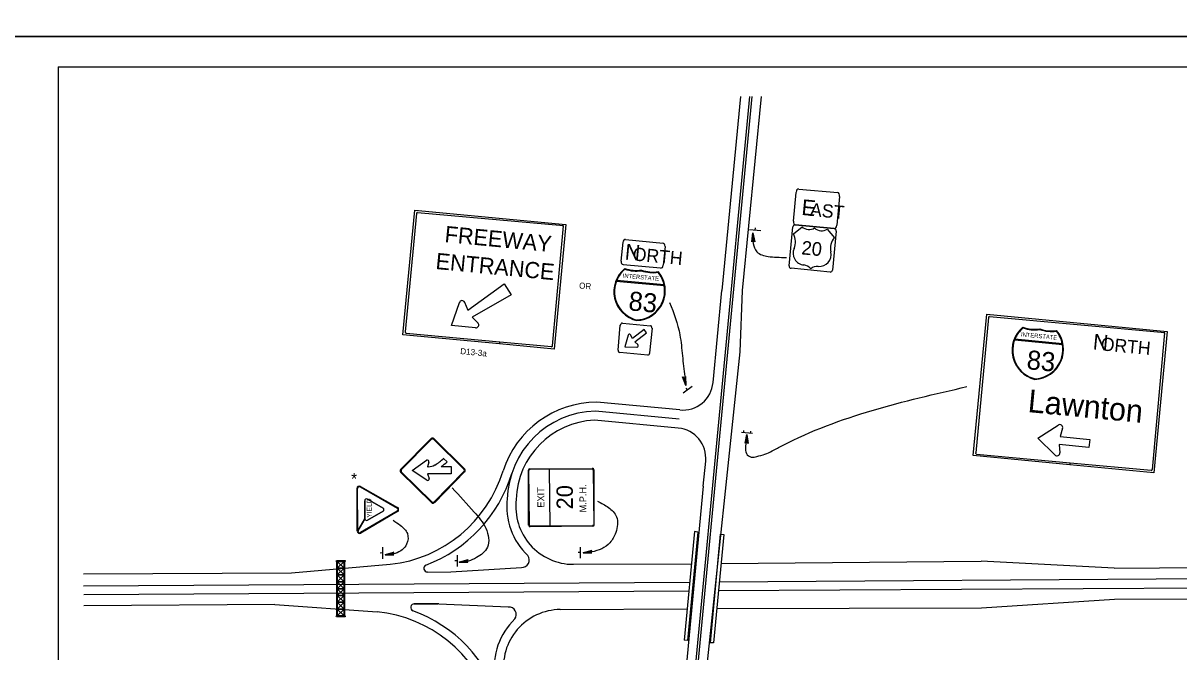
# Model space of a CAD drawing. Extents: x 644898 to 648326, y 298294 to 300670.
# Drawn here: x 647444 to 648015, y 299772 to 300083 of the extents above; entities that cross this region are included whole.
import ezdxf

# ---------------------------------------------------------------- set-up
doc = ezdxf.new("R2010")
doc.units = 0
for name, color, linetype in [('1', 7, 'Continuous'), ('2', 7, 'Continuous'), ('XCS-GRID-MIN', 7, 'Continuous')]:
    doc.layers.add(name, color=color, linetype=linetype)

msp = doc.modelspace()

# ---------------------------------------------------------------- linework, layer by layer
at = {"layer": '1'}
for q in [(648247.32, 300061.49), (647461.32, 299497.49)]:
    msp.add_line((647461.32, 300061.49), q, dxfattribs=at)
at = {"layer": '2'}
for p, q in [((647802.82, 300046.87), (647766.22, 299662.87)), ((647803.95, 300046.87), (647767.34, 299662.77)), ((647798.32, 300046.87), (647789.07, 299950.99)), ((647808.45, 300046.87), (647799.2, 299950.99)), ((647824.45, 299985.24), (647825.82, 299999.49)), ((647827.07, 300001.12), (647846.32, 299999.37)), ((647847.2, 299997.49), (647845.82, 299983.24)), ((647631.52, 299929.13), (647637.45, 299990.69)), ((647638.33, 299989.06), (647632.78, 299930.56)), ((647637.45, 299990.68), (647712.1, 299983.56)), ((647835.82, 299991.37), (647835.82, 299991.37)), ((647705.52, 299923.65), (647710.92, 299982.9)), ((647712.1, 299983.56), (647706.3, 299922.01)), ((647824.45, 299978.99), (647828.7, 299982.49)), ((647844.57, 299981.62), (647825.32, 299983.37)), ((647825.32, 299983.37), (647844.57, 299981.62)), ((647808.32, 299980.49), (647802.82, 299980.99)), ((647805.57, 299980.87), (647805.7, 299981.87)), ((647822.32, 299963.12), (647824.07, 299982.37)), ((647841.07, 299981.24), (647844.7, 299976.99)), ((647845.57, 299980.37), (647843.7, 299960.99)), ((647739.45, 299965.48), (647740.32, 299974.8)), ((647741.53, 299976.15), (647760.05, 299974.37)), ((647761.03, 299972.77), (647760.2, 299963.48)), ((647833.95, 299971.74), (647833.95, 299971.74)), ((647843.07, 299968.12), (647843.07, 299968.12)), ((647758.82, 299961.98), (647740.45, 299963.73)), ((647741.22, 299961.52), (647741.22, 299961.52)), ((647749.35, 299960.77), (647749.35, 299960.77)), ((647757.6, 299960.02), (647757.6, 299960.02)), ((647842.57, 299960.12), (647823.32, 299961.99)), ((647829.57, 299963.62), (647829.57, 299963.62)), ((647836.7, 299962.87), (647836.7, 299962.87)), ((647663.73, 299941.26), (647681.58, 299954.31)), ((647681.58, 299954.31), (647685.14, 299948.81)), ((647736.97, 299955.65), (647760.6, 299953.4)), ((647760.6, 299953.77), (647737.22, 299955.9)), ((647685.14, 299948.81), (647665.85, 299937.86)), ((647784.78, 299905.51), (647789.07, 299950.99)), ((647799.2, 299950.99), (647797.95, 299920.74)), ((647655.67, 299933.64), (647659.51, 299945.02)), ((647662.05, 299945.23), (647663.73, 299941.26)), ((647665.85, 299937.86), (647668.78, 299934.88)), ((647913.21, 299869.4), (647919.93, 299939.29)), ((647920.81, 299937.66), (647914.46, 299870.81)), ((647919.93, 299939.28), (648009.06, 299930.78)), ((647667.49, 299932.51), (647655.67, 299933.64)), ((647737.83, 299921.55), (647738.93, 299933.83)), ((647739.99, 299934.85), (647753.82, 299933.53)), ((647750.82, 299931.71), (647744.91, 299927.3)), ((647751.96, 299930.06), (647750.82, 299931.71)), ((647754.66, 299932.36), (647753.41, 299920.12)), ((647937.85, 299932.44), (647937.85, 299932.44)), ((647946.1, 299931.69), (647946.1, 299931.69)), ((647679.32, 299924.58), (647631.52, 299929.13)), ((647633.18, 299929.91), (647679.42, 299925.59)), ((647679.32, 299924.58), (647679.42, 299925.59)), ((647679.42, 299925.59), (647679.32, 299924.58)), ((647679.42, 299925.59), (647704.93, 299923.31)), ((647742.79, 299928.92), (647741.22, 299923.19)), ((647744.91, 299927.3), (647743.98, 299929.05)), ((647746.2, 299925.6), (647751.96, 299930.06)), ((647747.72, 299924.16), (647746.2, 299925.6)), ((647933.73, 299926.57), (647957.23, 299924.32)), ((647957.23, 299924.69), (647933.85, 299926.94)), ((647954.23, 299930.94), (647954.23, 299930.94)), ((648001.68, 299862.54), (648007.87, 299930.12)), ((648009.06, 299930.78), (648002.46, 299860.9)), ((647706.3, 299922.01), (647679.32, 299924.58)), ((647752.51, 299919.05), (647738.67, 299920.37)), ((647741.22, 299923.19), (647747.21, 299923.01)), ((647797.95, 299920.74), (647780.45, 299754.37)), ((647774.5, 299903.54), (647769.96, 299900.19)), ((647772.18, 299901.83), (647771.53, 299902.75)), ((647768, 299887.49), (647726.65, 299891.41)), ((647768.42, 299891.99), (647727.41, 299895.9)), ((647767.59, 299882.99), (647726.14, 299886.91)), ((647756.07, 299888.62), (647756.07, 299888.62)), ((647804.27, 299880.26), (647798.77, 299880.76)), ((647799.9, 299880.63), (647799.9, 299881.76)), ((647803.27, 299880.38), (647803.4, 299881.51)), ((647945.09, 299878.06), (647955.24, 299884.48)), ((647957.35, 299883.04), (647956.15, 299878.9)), ((647630.45, 299862.62), (647645.57, 299877.87)), ((647630.95, 299862.49), (647645.57, 299877.37)), ((647646.82, 299877.37), (647661.7, 299862.74)), ((647646.95, 299877.87), (647662.2, 299862.74)), ((647953.56, 299869.74), (647945.09, 299878.06)), ((647970.31, 299873.34), (647955.66, 299874.93)), ((647955.66, 299874.93), (647956.05, 299870.77)), ((647956.15, 299878.9), (647970.8, 299877.31)), ((647970.8, 299877.31), (647970.31, 299873.34)), ((647961.01, 299864.84), (647913.21, 299869.4)), ((647914.87, 299870.18), (647961.1, 299865.85)), ((647636.2, 299862.12), (647643.32, 299867.12)), ((647636.2, 299862.12), (647643.32, 299867.12)), ((647644.45, 299866.24), (647643.82, 299863.87)), ((647644.45, 299866.24), (647643.82, 299863.87)), ((647643.82, 299863.87), (647644.2, 299863.99)), ((647643.82, 299863.87), (647644.2, 299863.99)), ((647650.57, 299863.99), (647655.45, 299863.99)), ((647650.57, 299863.99), (647650.57, 299863.99)), ((647650.57, 299863.99), (647655.45, 299863.99)), ((647651.7, 299867.99), (647653.45, 299866.37)), ((647651.7, 299867.99), (647653.45, 299866.37)), ((647655.45, 299863.99), (647655.45, 299860.37)), ((647655.45, 299863.99), (647655.45, 299860.37)), ((647694.2, 299862.87), (647725.2, 299863.12)), ((647694.45, 299862.74), (647724.95, 299862.87)), ((647704.32, 299834.62), (647704.07, 299862.74)), ((647779.94, 299854.28), (647781.11, 299866.65)), ((647961.01, 299864.84), (647961.1, 299865.85)), ((647961.1, 299865.85), (647961.01, 299864.84)), ((648002.46, 299860.9), (647961.01, 299864.84)), ((647961.1, 299865.85), (648001.09, 299862.2)), ((647645.82, 299846.12), (647630.45, 299861.24)), ((647645.82, 299846.62), (647630.95, 299861.24)), ((647643.45, 299857.24), (647636.2, 299862.12)), ((647643.45, 299857.24), (647636.2, 299862.12)), ((647655.45, 299860.37), (647643.82, 299860.37)), ((647643.82, 299860.37), (647644.57, 299858.12)), ((647655.45, 299860.37), (647643.82, 299860.37)), ((647643.82, 299860.37), (647644.57, 299858.12)), ((647661.7, 299861.49), (647647.07, 299846.62)), ((647662.2, 299861.49), (647647.2, 299846.12)), ((647693.7, 299834.99), (647693.57, 299862.24)), ((647694.07, 299835.24), (647693.82, 299861.99)), ((647725.57, 299862.24), (647725.82, 299835.37)), ((647725.82, 299862.37), (647725.95, 299835.24)), ((647609.07, 299832.24), (647608.95, 299853.12)), ((647609.32, 299832.24), (647609.2, 299853.12)), ((647609.32, 299832.24), (647609.2, 299853.12)), ((647610.45, 299853.99), (647628.7, 299843.49)), ((647610.45, 299853.99), (647628.7, 299843.49)), ((647610.7, 299854.12), (647628.95, 299843.74)), ((647779.95, 299854.24), (647769.7, 299745.49)), ((647612.82, 299838.24), (647612.82, 299847.12)), ((647612.82, 299847.12), (647612.82, 299838.24)), ((647614.07, 299847.87), (647621.82, 299843.49)), ((647621.82, 299843.49), (647614.07, 299847.87)), ((647779.57, 299849.74), (647779.57, 299849.74)), ((647628.82, 299841.99), (647610.7, 299831.49)), ((647628.82, 299841.99), (647610.7, 299831.49)), ((647628.95, 299841.74), (647610.82, 299831.12)), ((647621.82, 299841.99), (647614.07, 299837.49)), ((647614.07, 299837.49), (647621.82, 299841.99)), ((647612.82, 299838.24), (647609.32, 299832.24)), ((647609.32, 299832.24), (647612.82, 299838.24)), ((647612.82, 299838.24), (647612.82, 299838.24)), ((647725.32, 299834.49), (647694.45, 299834.24)), ((647725.2, 299834.74), (647694.57, 299834.49)), ((647775.57, 299831.87), (647770.45, 299778.24)), ((647777.2, 299831.62), (647772.2, 299778.12)), ((647777.2, 299831.62), (647775.57, 299831.87)), ((647788.32, 299830.62), (647783.32, 299776.99)), ((647790.07, 299830.49), (647784.95, 299776.87)), ((647788.32, 299830.62), (647790.07, 299830.49)), ((647621.57, 299824.12), (647621.57, 299818.49)), ((647719.2, 299824.24), (647719.2, 299818.74)), ((647599.2, 299817.12), (647602.57, 299813.74)), ((647602.57, 299817.12), (647599.2, 299813.74)), ((647621.57, 299821.37), (647620.32, 299821.24)), ((647658.45, 299817.37), (647657.2, 299817.37)), ((647658.32, 299820.24), (647658.45, 299814.62)), ((647719.2, 299821.49), (647718.2, 299821.49)), ((647788.57, 299816.12), (647917.17, 299817.3)), ((647982.82, 299813.87), (647917.2, 299817.24)), ((647473.9, 299810.93), (647576.57, 299811.49)), ((647576.57, 299811.49), (647625.32, 299815.74)), ((647599.2, 299813.74), (647602.57, 299810.49)), ((647602.57, 299813.74), (647599.2, 299810.49)), ((647643.82, 299811.87), (647655.32, 299811.99)), ((647655.32, 299811.99), (647690.2, 299814.12)), ((647715.82, 299815.74), (647774.07, 299815.99)), ((647715.82, 299815.74), (647715.82, 299815.74)), ((647846.82, 299816.49), (647846.82, 299816.49)), ((647982.82, 299813.87), (648204.57, 299815.27)), ((647773.2, 299806.74), (647473.96, 299804.85)), ((647599.2, 299810.49), (647602.57, 299806.99)), ((647602.57, 299810.49), (647599.2, 299806.99)), ((647599.2, 299806.99), (647602.57, 299803.62)), ((647602.57, 299806.99), (647599.2, 299803.62)), ((648204.57, 299809.66), (647787.82, 299806.87)), ((647474.01, 299800.83), (647772.82, 299802.62)), ((647599.2, 299803.62), (647602.57, 299800.37)), ((647602.57, 299803.62), (647599.2, 299800.37)), ((647599.2, 299800.37), (647602.57, 299796.99)), ((647602.57, 299800.37), (647599.2, 299796.99)), ((647787.32, 299802.74), (648204.57, 299805.13)), ((647568.35, 299795.86), (647474.07, 299795.24)), ((647568.35, 299795.86), (647618.82, 299792.24)), ((647599.2, 299796.99), (647602.57, 299793.62)), ((647602.57, 299796.99), (647599.2, 299793.62)), ((647637.2, 299796.12), (647648.82, 299796.24)), ((647649.4, 299796.21), (647637.2, 299796.12)), ((647649.4, 299796.21), (647683.57, 299794.62)), ((647982.95, 299798.24), (647917.32, 299793.99)), ((648204.57, 299799.51), (647982.95, 299798.24)), ((647599.2, 299793.62), (647602.57, 299790.24)), ((647602.57, 299793.62), (647599.2, 299790.24)), ((647602.57, 299790.24), (647602.57, 299793.62)), ((647771.95, 299793.62), (647709.32, 299793.24)), ((647713.7, 299793.24), (647713.7, 299793.24)), ((647917.32, 299793.99), (647786.57, 299793.74)), ((647772.2, 299778.12), (647770.45, 299778.24)), ((647784.95, 299776.87), (647783.32, 299776.99))]:
    msp.add_line(p, q, dxfattribs=at)
for points in [[(647710.91, 299982.9), (647638.83, 299989.43)], [(647804.03, 299975.24), (647804.3, 299975.34), (647804.33, 299979.41), (647804.03, 299975.24), (647803.86, 299975.06), (647804.33, 299979.41), (647804.83, 299975.36), (647805.09, 299975.28), (647804.33, 299979.41), (647805.37, 299975.03), (647805.09, 299975.28)], [(648007.87, 299930.12), (647921.31, 299938.03)], [(647771.02, 299908.29), (647770.78, 299908.16), (647771.37, 299904.13), (647771.02, 299908.29), (647771.17, 299908.5), (647771.37, 299904.13), (647770.26, 299908.06), (647769.98, 299908.09), (647771.37, 299904.13), (647769.67, 299908.3), (647769.98, 299908.09)], [(647800.79, 299875.73), (647801.06, 299875.81), (647801.41, 299879.86), (647800.79, 299875.73), (647800.61, 299875.56), (647801.41, 299879.86), (647801.59, 299875.78), (647801.85, 299875.68), (647801.41, 299879.86), (647802.1, 299875.41), (647801.85, 299875.68)], [(647724.71, 299821.32), (647724.6, 299821.58), (647720.54, 299821.33), (647724.71, 299821.32), (647724.91, 299821.16), (647720.54, 299821.33), (647724.54, 299822.1), (647724.6, 299822.38), (647720.54, 299821.33), (647724.84, 299822.67), (647724.6, 299822.38)], [(647598.82, 299817.12), (647598.82, 299790.24)], [(647602.57, 299817.49), (647599.2, 299817.49)], [(647599.2, 299790.24), (647602.57, 299790.24), (647602.57, 299817.12), (647599.2, 299817.12), (647599.2, 299790.24)], [(647602.95, 299790.24), (647602.95, 299817.12)], [(647626.97, 299820.41), (647626.86, 299820.67), (647622.8, 299820.42), (647626.97, 299820.41), (647627.17, 299820.26), (647622.8, 299820.42), (647626.8, 299821.2), (647626.86, 299821.47), (647622.8, 299820.42), (647627.1, 299821.76), (647626.86, 299821.47)], [(647663.53, 299816.72), (647663.41, 299816.98), (647659.35, 299816.73), (647663.53, 299816.72), (647663.72, 299816.56), (647659.35, 299816.73), (647663.36, 299817.5), (647663.42, 299817.78), (647659.35, 299816.73), (647663.65, 299818.07), (647663.42, 299817.78)], [(647599.2, 299789.87), (647602.57, 299789.87)]]:
    msp.add_lwpolyline(points, dxfattribs=at)
for points in [[(647599.2, 299813.74), (647599.2, 299817.12), (647602.57, 299817.12), (647602.57, 299813.74)], [(647599.2, 299810.49), (647599.2, 299813.74), (647602.57, 299813.74), (647602.57, 299810.49)], [(647599.2, 299806.99), (647599.2, 299810.49), (647602.57, 299810.49), (647602.57, 299806.99)], [(647599.2, 299803.62), (647599.2, 299806.99), (647602.57, 299806.99), (647602.57, 299803.62)], [(647599.2, 299800.37), (647599.2, 299803.62), (647602.57, 299803.62), (647602.57, 299800.37)], [(647599.2, 299796.99), (647599.2, 299800.37), (647602.57, 299800.37), (647602.57, 299796.99)], [(647599.2, 299793.62), (647599.2, 299796.99), (647602.57, 299796.99), (647602.57, 299793.62)], [(647599.2, 299790.24), (647599.2, 299793.62), (647602.57, 299793.62), (647602.57, 299790.24)]]:
    msp.add_lwpolyline(points, close=True, dxfattribs=at)
for centre in [(647599.02, 299817.33), (647602.8, 299817.33), (647599.02, 299790.03), (647602.8, 299790.03)]:
    msp.add_circle(centre, 0.301, dxfattribs=at)
for centre, radius, start, end in [((647638.77, 299988.98), 0.528, 84.2894, 175.6013), ((647825.22, 299982.28), 1.07, 84.5662, 174.5662), ((647832.17, 299986.34), 5.23, 227.7022, 301.4303), ((647817.34, 299975.02), 8.13, 336.3952, 29.141), ((647838.41, 299985.74), 5.23, 227.7022, 301.4303), ((647850.84, 299971.83), 8.13, 139.9915, 192.7373), ((647844.48, 299980.45), 1.07, 354.5662, 84.5662), ((647830.11, 299969.4), 5.82, 156.0183, 264.5615), ((647837.24, 299968.72), 5.82, 264.571, 13.1142), ((647750.56, 299950.48), 14.78, 129.5662, 256.4361), ((647750.56, 299950.48), 14.47, 130.2586, 157.7735), ((647746.86, 299977.87), 16.98, 250.3162, 278.8163), ((647746.86, 299977.87), 17.29, 250.9067, 278.5552), ((647746.39, 299950.88), 14.78, 272.6963, 39.5662), ((647755.19, 299977.08), 17.29, 250.5773, 278.2258), ((647755.19, 299977.08), 16.98, 250.3162, 278.8163), ((647746.39, 299950.88), 14.47, 11.359, 38.8739), ((647823.38, 299963.02), 1.07, 174.5662, 264.5662), ((647829.09, 299958.7), 4.93, 38.2937, 84.5662), ((647836.23, 299958.02), 4.93, 84.5662, 130.8388), ((647842.65, 299961.19), 1.07, 264.5662, 354.5662), ((647750.56, 299950.48), 14.47, 159.0531, 256.4361), ((647746.39, 299950.88), 14.47, 272.6964, 10.0794), ((647660.83, 299944.59), 1.4, 21.1732, 165.0799), ((647921.25, 299937.59), 0.528, 84.2894, 175.6013), ((647667.64, 299933.94), 1.4, 262.7848, 43.4503), ((647947.18, 299921.44), 14.78, 129.5662, 256.4361), ((647947.18, 299921.44), 14.47, 130.2586, 157.7735), ((647943.48, 299948.83), 16.98, 250.3162, 278.8163), ((647943.48, 299948.83), 17.29, 250.9067, 278.5552), ((647943.02, 299921.84), 14.78, 272.6963, 39.5662), ((647951.81, 299948.04), 17.29, 250.5773, 278.2258), ((647951.81, 299948.04), 16.98, 250.3162, 278.8163), ((647743.4, 299928.8), 0.625, 28.144, 164.5177), ((647947.18, 299921.44), 14.47, 159.0531, 256.4361), ((647943.02, 299921.84), 14.47, 11.359, 38.8739), ((648007.36, 299929.49), 0.528, 354.144, 84.5077), ((647747.23, 299923.67), 0.625, 267.0622, 48.6931), ((647943.02, 299921.84), 14.47, 272.6964, 10.0794), ((647769.84, 299906.92), 15, 264.5486, 354.6082), ((647727.86, 299846.67), 49.23, 90.5215, 161.9821), ((647727.86, 299846.67), 44.75, 91.5424, 178.5076), ((647727.86, 299846.67), 40.27, 92.4413, 178.5076), ((647766.18, 299868.06), 15, 354.6082, 84.6064), ((647956, 299883.32), 1.4, 342.1199, 126.0266), ((647646.23, 299877.17), 0.932, 45.3747, 135.3747), ((647646.24, 299876.78), 0.854, 45.3747, 135.3747), ((647954.57, 299870.75), 1.4, 223.7315, 4.397), ((647631.17, 299861.91), 0.932, 135.3747, 225.3747), ((647643.71, 299866.44), 0.776, 344.1725, 122.044), ((647643.71, 299866.44), 0.776, 344.1725, 122.044), ((647644.19, 299870.23), 6.31, 270.1504, 300.2643), ((647644.19, 299870.23), 6.31, 270.1504, 300.2643), ((647636.5, 299883.74), 21.86, 299.8117, 314.2596), ((647636.5, 299883.74), 21.86, 299.8117, 314.2596), ((647636.08, 299884.24), 24.91, 305.5161, 314.2639), ((647636.08, 299884.24), 24.91, 305.5161, 314.2639), ((647661.11, 299862.1), 0.854, 315.3747, 45.3747), ((647661.49, 299862.11), 0.932, 315.3747, 45.3747), ((647618.21, 299880.98), 65.66, 276.2555, 343.1031), ((647631.56, 299861.91), 0.854, 135.3747, 225.3747), ((647618.21, 299880.98), 70.14, 290.6825, 343.1031), ((647643.76, 299857.89), 0.777, 238.8177, 16.4645), ((647643.76, 299857.89), 0.777, 238.8177, 16.4645), ((647610.08, 299853.16), 1.18, 60.3746, 180.3747), ((647610.08, 299853.16), 0.871, 60.3746, 180.3747), ((647610.08, 299853.16), 0.871, 60.3746, 180.3747), ((647613.6, 299847.15), 0.871, 60.3747, 180.3747), ((647613.6, 299847.15), 0.871, 60.3747, 180.3747), ((647646.43, 299846.85), 0.932, 225.3747, 315.3747), ((647646.43, 299847.23), 0.854, 225.3747, 315.3747), ((647715.75, 299844.08), 32.86, 172.6333, 226.9648), ((647715.75, 299844.08), 28.38, 172.6333, 270.1695), ((647621.36, 299842.74), 0.871, 300.3747, 60.3746), ((647621.36, 299842.74), 0.871, 300.3747, 60.3746), ((647628.33, 299842.78), 0.871, 300.3747, 60.3746), ((647628.33, 299842.78), 0.871, 300.3747, 60.3746), ((647628.33, 299842.78), 1.18, 300.3747, 60.3746), ((647613.66, 299838.23), 0.871, 180.3746, 300.3746), ((647613.66, 299838.23), 0.871, 180.3747, 300.3746), ((647610.21, 299832.17), 1.18, 180.3747, 300.3747), ((647610.21, 299832.17), 0.871, 180.3746, 300.3747), ((647610.21, 299832.17), 0.871, 180.3746, 300.3747), ((647690.26, 299817.88), 3.76, 268.4553, 35.5225), ((647643.76, 299813.73), 1.81, 115.1781, 270.4845), ((647637.24, 299794.39), 1.81, 90.2638, 245.5703), ((647683.8, 299790.85), 3.76, 325.2259, 92.293), ((647612.58, 299726.81), 65.66, 17.6452, 84.4929), ((647612.58, 299726.81), 70.14, 17.6452, 70.0659), ((647709.62, 299764.98), 32.86, 133.7836, 188.115), ((647709.62, 299764.98), 28.38, 90.5788, 188.115)]:
    msp.add_arc(centre, radius, start, end, dxfattribs=at)
for centre, major_axis, ratio, start_param, end_param in [((647826.84, 299999.4), (-0.17, -1.78), 0.6, 3.141593, 4.712389), ((647846.11, 299997.57), (0.17, 1.78), 0.6, 4.712389, 6.283185), ((647710.41, 299982.26), (0, 0.528), 0.987556, 4.610182, 6.187326), ((647825.49, 299985.14), (-0.17, -1.78), 0.6, 4.712389, 6.283185), ((647844.75, 299983.3), (0.17, 1.78), 0.6, 3.141593, 4.712389), ((647741.44, 299974.66), (0.14, 1.52), 0.760552, 6.279242, 7.850039), ((647759.89, 299972.88), (0.14, 1.52), 0.767529, 4.711578, 6.282375), ((647740.55, 299965.36), (-0.15, -1.55), 0.769266, 4.712389, 6.283185), ((647758.98, 299963.6), (0.15, 1.55), 0.769266, 3.141593, 4.712389), ((647739.86, 299933.67), (-0.11, -1.16), 0.769266, 3.141593, 4.712389), ((647753.69, 299932.42), (0.11, 1.16), 0.769266, 4.712389, 6.283185), ((647633.26, 299930.49), (-0.556, 0), 0.992604, 6.180104, 7.77084), ((647705, 299923.71), (0, -0.496), 0.993424, 6.192525, 7.765974), ((647738.75, 299921.49), (-0.11, -1.16), 0.769266, 4.712389, 6.283185), ((647752.58, 299920.24), (0.11, 1.16), 0.769266, 3.141593, 4.712389), ((647914.94, 299870.75), (-0.558, 0), 0.963153, 6.180104, 7.77084), ((647694.22, 299862.23), (0.005, -0.717), 0.9, 3.141593, 4.712389), ((647694.41, 299862.02), (0.004, -0.657), 0.9, 3.141593, 4.712389), ((647725.01, 299862.22), (-0.004, 0.657), 0.9, 4.712389, 6.283185), ((647725.19, 299862.44), (-0.005, 0.717), 0.9, 4.712389, 6.283185), ((648001.16, 299862.6), (0.496, 0), 0.990562, 4.621729, 6.195178), ((647694.4, 299834.99), (0.005, -0.717), 0.9, 4.712389, 6.283185), ((647694.58, 299835.2), (0.004, -0.657), 0.9, 4.712389, 6.283185), ((647725.18, 299835.4), (-0.004, 0.657), 0.9, 3.141593, 4.712389), ((647725.37, 299835.19), (0.005, -0.717), 0.9, 0, 1.570796)]:
    msp.add_ellipse(centre, major_axis=major_axis, ratio=ratio, start_param=start_param, end_param=end_param, dxfattribs=at)
for points in [[(647804.32, 299979.24), (647804.57, 299974.25), (647806.39, 299970.13), (647811.96, 299967.8), (647816.2, 299967.49), (647820.95, 299967.24)], [(647763.33, 299945.12), (647768.37, 299929.05), (647769.62, 299918.72), (647770.87, 299908.48), (647771.24, 299905.36)], [(647801.28, 299878.31), (647801.19, 299876.72), (647801.22, 299870.5), (647803.64, 299868.65), (647806.39, 299869.01), (647810.4, 299870.09), (647813.96, 299871.75), (647819.04, 299874.43), (647910.14, 299903.5)], [(647655.95, 299853.49), (647666.82, 299841.49), (647672.57, 299833.49), (647673.32, 299824.12), (647668.02, 299819.03), (647663.97, 299817.34), (647661.67, 299817)], [(647727.7, 299846.87), (647733.1, 299843.75), (647737.07, 299839.24), (647736.7, 299831.37), (647733.82, 299826.37), (647724.88, 299821.83), (647721.77, 299821.45)], [(647626.82, 299837.49), (647630.32, 299834.99), (647633.82, 299830.87), (647633.45, 299825.62), (647631.32, 299822.87), (647627.82, 299821.12), (647625.12, 299820.61)]]:
    msp.add_spline(points, degree=3, dxfattribs=at)
at = {"layer": 'XCS-GRID-MIN'}
for points in [[(647421.32, 300670.49), (648262.32, 300670.49), (648262.32, 300076.49), (647421.32, 300076.49)], [(647421.32, 300076.49), (648262.32, 300076.49), (648262.32, 299482.49), (647421.32, 299482.49)]]:
    msp.add_lwpolyline(points, close=True, dxfattribs=at)

# ---------------------------------------------------------------- texts
at = {"layer": '2'}
for s, height, rotation, p in [('E', 7.75, 354.5817, (647828.2, 299988.37)), ('AST', 6.5, 354.5683, (647832.44, 299987.87)), ('FREEWAY', 8, 354.5683, (647651.98, 299974.96)), ('N', 7.75, 354.5817, (647740.98, 299966.38)), ('ORTH', 6.5, 354.5683, (647744.87, 299965.88)), ('20', 6.75, 354.5663, (647828.2, 299968.87)), ('ENTRANCE', 8, 354.5683, (647647.5, 299961.65)), ('OR', 3, 354.4706, (647718.5, 299952.03)), ('INTERSTATE', 2.089, 354.5668, (647740.1, 299957.4)), ('83', 9.406, 354.5658, (647742.72, 299941.27)), ('INTERSTATE', 2.089, 354.5668, (647936.73, 299928.32)), ('N', 7.75, 354.5817, (647972.09, 299921.94)), ('ORTH', 6.5, 354.5683, (647975.98, 299921.44)), ('D13-3a', 3, 354.4706, (647659.81, 299919.62)), ('83', 9.406, 354.5658, (647939.35, 299912.19)), ('Lawnton', 11.25, 354.5683, (647939.87, 299890.96)), ('EXIT', 3.387, 90.3745, (647701.45, 299843.74)), ('20', 8.061, 90.3746, (647715.57, 299842.87)), ('M.P.H.', 3.387, 90.3746, (647722.2, 299841.37)), ('YIELD', 2.383, 90.3738, (647616.19, 299838.74))]:
    msp.add_text(s, height=height, rotation=rotation, dxfattribs=at).set_placement(p)
msp.add_text('*', height=5.85, dxfattribs=at).set_placement((647605.98, 299855.03))

doc.saveas('drawing.dxf')
